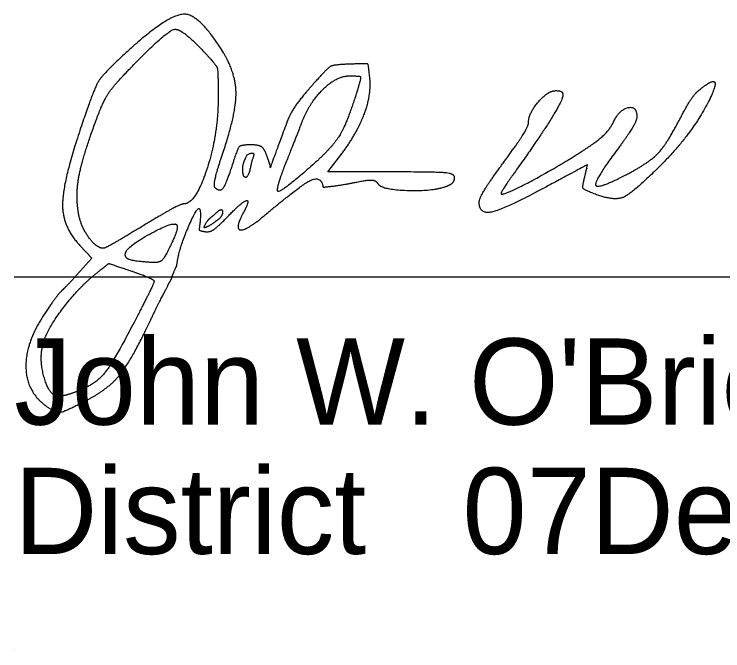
# Model space of a CAD drawing. Extents: x 0 to 34, y 0 to 22.
# Drawn here: x 24.528 to 25.679, y 8.065 to 9.099 of the extents above; entities that cross this region are included whole.
import ezdxf

# ---------------------------------------------------------------- set-up
doc = ezdxf.new("R2010")
doc.units = 0
doc.layers.add('SH_Data', color=7, linetype='Continuous')
doc.layers.add('SH_Text', color=7, linetype='Continuous')

msp = doc.modelspace()

# ---------------------------------------------------------------- linework, layer by layer
at = {"layer": 'SH_Data'}
for p, q in [((24.5279, 8.6721), (28.0279, 8.6721)), ((24.5279, 8.0649), (24.5279, 8.0649))]:
    msp.add_line(p, q, dxfattribs=at)
at = {"layer": 'SH_Text'}
for points in [[(25.1404, 8.8424), (25.0375, 8.8424), (25.0558, 8.8664)], [(24.6346, 8.7231), (24.654, 8.7024), (24.6346, 8.6807)]]:
    msp.add_lwpolyline(points, dxfattribs=at)
for points in [[(24.8676, 9.036), (24.8304, 9.0969), (24.781, 9.1001), (24.7199, 9.0453)], [(24.7219, 9.0164), (24.7758, 9.0717), (24.8, 9.0762), (24.836, 9.0376)], [(24.7199, 9.0453), (24.6737, 9.004), (24.656, 8.9751), (24.6319, 8.9015)], [(24.836, 9.0376), (24.8564, 9.0157), (24.8592, 9.0068), (24.8592, 8.9635)], [(24.8663, 8.8715), (24.888, 8.9355), (24.8885, 9.0017), (24.8676, 9.036)], [(24.6595, 8.9224), (24.672, 8.9566), (24.69, 8.9837), (24.7219, 9.0164)], [(25.0723, 9.0174), (25.0465, 9.0166), (25.0363, 9.0107), (25.0106, 8.9817)], [(25.1056, 8.994), (25.1034, 9.0168), (25.1012, 9.0184), (25.0723, 9.0174)], [(24.9955, 8.9235), (25.008, 8.9557), (25.052, 8.9984), (25.0726, 8.9984)], [(25.0558, 8.8664), (25.0834, 8.9026), (25.1083, 8.9665), (25.1056, 8.994)], [(25.0726, 8.9984), (25.0893, 8.9984), (25.0915, 8.9957), (25.0869, 8.9804)], [(25.64, 8.975), (25.6828, 9.0106), (25.629, 8.9042), (25.5787, 8.854)], [(25.0106, 8.9817), (24.9936, 8.9625), (24.976, 8.9369), (24.9715, 8.9247)], [(25.0869, 8.9804), (25.0699, 8.9246), (25.0454, 8.8827), (25.013, 8.8541)], [(25.4192, 8.9672), (25.4192, 8.9594), (25.3786, 8.8945), (25.3398, 8.8404)], [(25.3632, 8.9224), (25.3632, 8.9375), (25.3949, 8.9744), (25.4078, 8.9744)], [(25.4078, 8.9744), (25.4141, 8.9744), (25.4192, 8.9712), (25.4192, 8.9672)], [(25.611, 8.9319), (25.6205, 8.9503), (25.6335, 8.9697), (25.64, 8.975)], [(24.8592, 8.9635), (24.8592, 8.9036), (24.8225, 8.7904), (24.803, 8.7904)], [(25.5007, 8.9224), (25.5102, 8.9432), (25.5392, 8.9503), (25.5392, 8.9319)], [(25.5392, 8.9319), (25.5392, 8.9261), (25.5248, 8.902), (25.5072, 8.8783)], [(25.5203, 8.837), (25.5584, 8.8567), (25.5884, 8.888), (25.611, 8.9319)], [(24.6328, 8.773), (24.6272, 8.8023), (24.6384, 8.865), (24.6595, 8.9224)], [(24.9715, 8.9247), (24.9427, 8.8471), (24.9449, 8.8508), (24.9381, 8.8693)], [(24.9722, 8.8644), (24.9814, 8.8875), (24.9919, 8.9141), (24.9955, 8.9235)], [(25.3232, 8.8584), (25.3452, 8.8882), (25.3632, 8.917), (25.3632, 8.9224)], [(25.4494, 8.8755), (25.4726, 8.8903), (25.4957, 8.9114), (25.5007, 8.9224)], [(24.6319, 8.9015), (24.6059, 8.8223), (24.607, 8.7525), (24.6346, 8.7231)], [(24.9121, 8.8864), (24.8965, 8.8864), (24.8905, 8.8803), (24.8829, 8.8564)], [(24.9381, 8.8693), (24.934, 8.8804), (24.9249, 8.8864), (24.9121, 8.8864)], [(25.3196, 8.8064), (25.3278, 8.8064), (25.4081, 8.8492), (25.4494, 8.8755)], [(25.5072, 8.8783), (25.47, 8.8285), (25.4747, 8.8136), (25.5203, 8.837)], [(24.8545, 8.8165), (24.8517, 8.8193), (24.8571, 8.844), (24.8663, 8.8715)], [(24.8992, 8.846), (24.8992, 8.8501), (24.8998, 8.8557), (24.9062, 8.8704)], [(24.9062, 8.8704), (24.9197, 8.877), (24.913, 8.858), (24.9118, 8.8501)], [(25.013, 8.8541), (24.962, 8.8093), (24.9513, 8.812), (24.9722, 8.8644)], [(24.8829, 8.8564), (24.8723, 8.8232), (24.8621, 8.8089), (24.8545, 8.8165)], [(25.2832, 8.7933), (25.2832, 8.7993), (25.3012, 8.8286), (25.3232, 8.8584)], [(25.4546, 8.8347), (25.4595, 8.8542), (25.4579, 8.8538), (25.3928, 8.8186)], [(25.5787, 8.854), (25.5329, 8.8083), (25.5023, 8.7946), (25.4719, 8.8062)], [(24.9118, 8.8501), (24.9078, 8.8328), (24.8992, 8.8344), (24.8992, 8.846)], [(25.2432, 8.8333), (25.2432, 8.8397), (25.2122, 8.8424), (25.1404, 8.8424)], [(25.3398, 8.8404), (25.3264, 8.8217), (25.3173, 8.8064), (25.3196, 8.8064)], [(24.9324, 8.7701), (24.9663, 8.7987), (25.0264, 8.8429), (25.0295, 8.8176)], [(25.0843, 8.826), (25.1028, 8.8297), (25.1154, 8.8287), (25.1188, 8.8231)], [(25.2306, 8.8193), (25.2375, 8.822), (25.2432, 8.8283), (25.2432, 8.8333)], [(25.4719, 8.8062), (25.4533, 8.8133), (25.4504, 8.818), (25.4546, 8.8347)], [(25.0295, 8.8176), (25.0437, 8.819), (25.0683, 8.8227), (25.0843, 8.826)], [(25.1188, 8.8231), (25.1245, 8.8139), (25.209, 8.811), (25.2306, 8.8193)], [(25.3928, 8.8186), (25.3258, 8.7824), (25.2832, 8.7726), (25.2832, 8.7933)], [(24.8708, 8.766), (24.8973, 8.7936), (24.9119, 8.7982), (24.8995, 8.7749)], [(24.803, 8.7904), (24.7991, 8.7904), (24.7691, 8.7742), (24.7365, 8.7544)], [(24.792, 8.6902), (24.7951, 8.7192), (24.8361, 8.8086), (24.8283, 8.7479)], [(24.6725, 8.7184), (24.6619, 8.7184), (24.6366, 8.7532), (24.6328, 8.773)], [(24.841, 8.7615), (24.8436, 8.7653), (24.8482, 8.7693), (24.8544, 8.7744)], [(24.8544, 8.7744), (24.8647, 8.7848), (24.8678, 8.7738), (24.8603, 8.7658)], [(24.8995, 8.7749), (24.886, 8.7496), (24.9047, 8.7469), (24.9324, 8.7701)], [(24.8283, 8.7479), (24.8419, 8.743), (24.8569, 8.7514), (24.8708, 8.766)], [(24.8603, 8.7658), (24.8459, 8.7551), (24.833, 8.7497), (24.841, 8.7615)], [(24.7365, 8.7544), (24.7039, 8.7346), (24.6751, 8.7184), (24.6725, 8.7184)], [(24.709, 8.7116), (24.7125, 8.7221), (24.786, 8.7623), (24.7916, 8.7568)], [(24.7916, 8.7568), (24.794, 8.7544), (24.7897, 8.7394), (24.7821, 8.7234)], [(24.7821, 8.7234), (24.7724, 8.7031), (24.7633, 8.6947), (24.7518, 8.6954)], [(24.7518, 8.6954), (24.7233, 8.697), (24.7062, 8.7035), (24.709, 8.7116)], [(24.6594, 8.6763), (24.6806, 8.6935), (24.6826, 8.6937), (24.7183, 8.6815)], [(24.7792, 8.6617), (24.7828, 8.6668), (24.7859, 8.6773), (24.792, 8.6902)], [(24.6346, 8.6807), (24.624, 8.6687), (24.6112, 8.6552), (24.6063, 8.6507)], [(24.7183, 8.6815), (24.7386, 8.6746), (24.7552, 8.6671), (24.7552, 8.6649)], [(24.5745, 8.5623), (24.5802, 8.585), (24.631, 8.6531), (24.6594, 8.6763)], [(24.7552, 8.6649), (24.7552, 8.6627), (24.7405, 8.6326), (24.7226, 8.5981)], [(24.7491, 8.6011), (24.7618, 8.628), (24.7762, 8.6548), (24.7792, 8.6617)], [(24.6063, 8.6507), (24.6013, 8.6461), (24.5878, 8.6281), (24.5763, 8.6106)], [(24.5763, 8.6106), (24.5453, 8.5637), (24.5487, 8.4831), (24.5824, 8.4605)], [(24.7226, 8.5981), (24.688, 8.5317), (24.6592, 8.4971), (24.6287, 8.4855)], [(24.6426, 8.4701), (24.6803, 8.4893), (24.7185, 8.5363), (24.7491, 8.6011)], [(24.599, 8.4784), (24.5855, 8.4784), (24.5682, 8.5374), (24.5745, 8.5623)], [(24.6287, 8.4855), (24.6185, 8.4816), (24.6052, 8.4784), (24.599, 8.4784)], [(24.5824, 8.4605), (24.5964, 8.4512), (24.6097, 8.4533), (24.6426, 8.4701)]]:
    msp.add_open_spline(points, degree=2, dxfattribs=at)

# ---------------------------------------------------------------- texts
for s, p in [("John W. O'Brien", (24.5279, 8.4321)), ('District       Deputy Director', (24.5279, 8.2221)), ('              07', (24.5279, 8.2221))]:
    msp.add_text(s, height=0.14, dxfattribs=at).set_placement(p)

doc.saveas('drawing.dxf')
